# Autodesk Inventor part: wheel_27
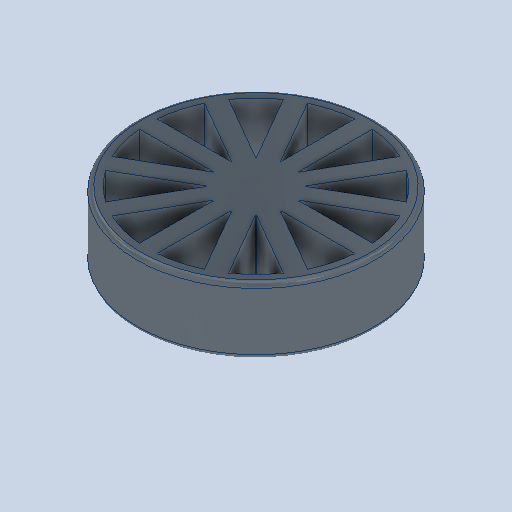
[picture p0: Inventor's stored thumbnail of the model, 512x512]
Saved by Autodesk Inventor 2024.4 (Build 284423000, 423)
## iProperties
Created: 2025-07
Part Number: wheel_27
Material: Generic
Document SubType Name: Modeling
Designer: AdminForWorker
Density: 1 g/cm^3
Appearance: Default
Title: wheel_27 v1
Author: AdminForWorker
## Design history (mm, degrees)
feature "untitled"
body "Solid1"
